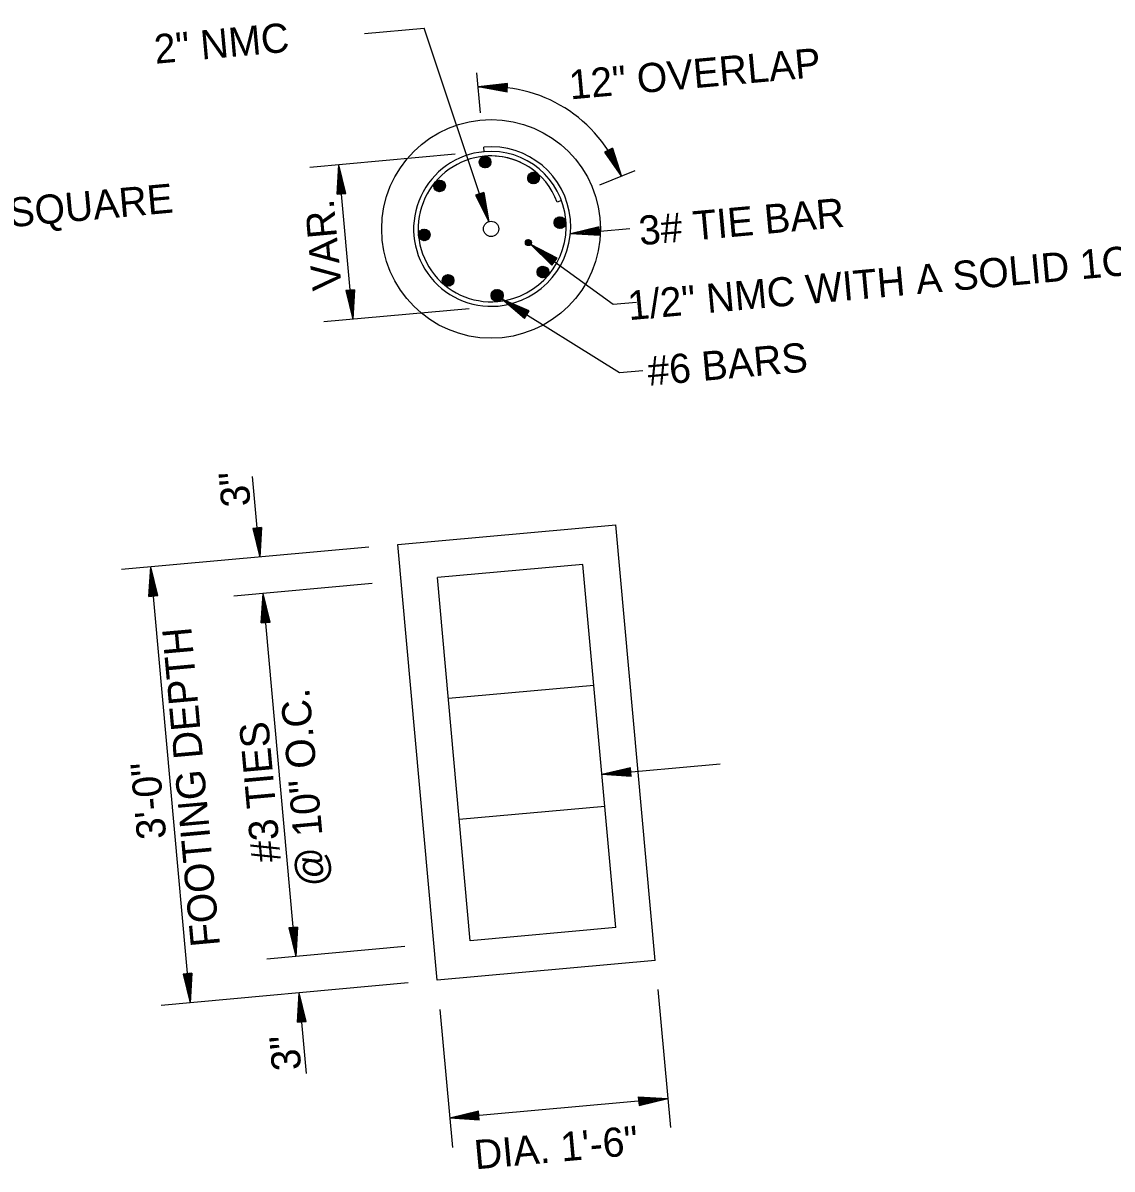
# Model space of a CAD drawing. Extents: x 1277218 to 1279252, y 196860 to 197529.
# Drawn here: x 1278789.6 to 1278960.9, y 197298.4 to 197478.8 of the extents above; entities that cross this region are included whole.
import ezdxf

# ---------------------------------------------------------------- set-up
doc = ezdxf.new("R2010")
doc.units = 0
doc.layers.add('R_Point Sym', color=7, linetype='Continuous')

msp = doc.modelspace()

# ---------------------------------------------------------------- linework, layer by layer
at = {"layer": 'R_Point Sym'}
for p, q in [((1278843.34, 197477.09), (1278852.69, 197477.93)), ((1278862.85, 197447.49), (1278852.69, 197477.93)), ((1278861.57, 197464.64), (1278861, 197470.9)), ((1278865.82, 197469.23), (1278861.21, 197468.71)), ((1278865.77, 197467.86), (1278861.21, 197468.71)), ((1278865.82, 197469.12), (1278861.98, 197468.68)), ((1278865.78, 197467.97), (1278861.98, 197468.68)), ((1278865.81, 197469), (1278862.76, 197468.66)), ((1278865.78, 197468.09), (1278862.76, 197468.66)), ((1278865.81, 197468.89), (1278863.53, 197468.63)), ((1278865.78, 197468.2), (1278863.53, 197468.63)), ((1278865.8, 197468.77), (1278864.31, 197468.6)), ((1278865.79, 197468.32), (1278864.31, 197468.6)), ((1278865.8, 197468.65), (1278865.07, 197468.57)), ((1278865.79, 197468.44), (1278865.07, 197468.57)), ((1278865.77, 197467.86), (1278865.82, 197469.23)), ((1278862.13, 197458.5), (1278862.06, 197459.22)), ((1278882.31, 197459.05), (1278881.07, 197458.44)), ((1278881.79, 197458.79), (1278882.01, 197458.09)), ((1278881.89, 197458.84), (1278882.35, 197457.4)), ((1278882, 197458.89), (1278882.69, 197456.71)), ((1278882.1, 197458.94), (1278883.03, 197456.02)), ((1278882.21, 197459), (1278883.38, 197455.31)), ((1278882.31, 197459.05), (1278883.71, 197454.62)), ((1278857.56, 197458.09), (1278834.7, 197456.02)), ((1278861.36, 197456.92), (1278862.07, 197457.77)), ((1278861.37, 197456.75), (1278862.23, 197457.79)), ((1278861.4, 197456.61), (1278862.38, 197457.78)), ((1278861.4, 197457.15), (1278861.85, 197457.68)), ((1278861.44, 197456.48), (1278862.51, 197457.76)), ((1278861.5, 197456.38), (1278862.63, 197457.72)), ((1278861.57, 197456.28), (1278862.73, 197457.67)), ((1278861.65, 197456.2), (1278862.83, 197457.61)), ((1278861.74, 197456.13), (1278862.92, 197457.53)), ((1278861.84, 197456.06), (1278862.99, 197457.45)), ((1278861.95, 197456.01), (1278863.06, 197457.35)), ((1278862.07, 197455.98), (1278863.12, 197457.24)), ((1278862.2, 197455.96), (1278863.16, 197457.11)), ((1278862.35, 197455.96), (1278863.19, 197456.96)), ((1278881.07, 197458.44), (1278883.71, 197454.62)), ((1278881.18, 197458.49), (1278883.38, 197455.31)), ((1278881.28, 197458.54), (1278883.03, 197456.02)), ((1278881.39, 197458.59), (1278882.69, 197456.71)), ((1278881.49, 197458.64), (1278882.35, 197457.4)), ((1278881.6, 197458.7), (1278882.01, 197458.09)), ((1278839, 197451.8), (1278839.27, 197456.43)), ((1278839.12, 197451.81), (1278839.34, 197455.67)), ((1278841.47, 197432.14), (1278839.27, 197456.43)), ((1278840.37, 197451.92), (1278839.27, 197456.43)), ((1278840.26, 197451.91), (1278839.34, 197455.67)), ((1278862.53, 197455.99), (1278863.19, 197456.79)), ((1278862.76, 197456.09), (1278863.13, 197456.53)), ((1278868.98, 197454.35), (1278869.74, 197455.26)), ((1278868.99, 197454.19), (1278869.9, 197455.27)), ((1278869, 197454.56), (1278869.54, 197455.2)), ((1278869.03, 197454.05), (1278870.04, 197455.26)), ((1278869.08, 197453.93), (1278870.16, 197455.23)), ((1278869.14, 197453.83), (1278870.28, 197455.19)), ((1278885.84, 197455.48), (1278880.26, 197453.23)), ((1278839.23, 197451.82), (1278839.41, 197454.88)), ((1278839.35, 197451.83), (1278839.48, 197454.12)), ((1278840.14, 197451.9), (1278839.41, 197454.88)), ((1278839.46, 197451.84), (1278839.55, 197453.35)), ((1278840.03, 197451.89), (1278839.48, 197454.12)), ((1278839.91, 197451.88), (1278839.55, 197453.35)), ((1278854.2, 197453.08), (1278855, 197454.03)), ((1278854.21, 197453.27), (1278854.81, 197453.98)), ((1278854.22, 197452.92), (1278855.15, 197454.04)), ((1278854.26, 197452.79), (1278855.29, 197454.02)), ((1278854.32, 197452.68), (1278855.41, 197453.99)), ((1278854.33, 197453.59), (1278854.52, 197453.81)), ((1278854.38, 197452.57), (1278855.52, 197453.94)), ((1278854.46, 197452.48), (1278855.63, 197453.89)), ((1278854.54, 197452.41), (1278855.72, 197453.82)), ((1278854.64, 197452.34), (1278855.8, 197453.74)), ((1278854.74, 197452.28), (1278855.87, 197453.65)), ((1278854.85, 197452.24), (1278855.94, 197453.54)), ((1278854.98, 197452.21), (1278855.99, 197453.42)), ((1278869.22, 197453.74), (1278870.38, 197455.13)), ((1278869.3, 197453.66), (1278870.47, 197455.07)), ((1278869.39, 197453.59), (1278870.56, 197454.99)), ((1278869.49, 197453.53), (1278870.63, 197454.9)), ((1278869.6, 197453.48), (1278870.7, 197454.8)), ((1278869.72, 197453.45), (1278870.75, 197454.69)), ((1278869.86, 197453.44), (1278870.79, 197454.55)), ((1278870.02, 197453.44), (1278870.81, 197454.4)), ((1278870.2, 197453.49), (1278870.8, 197454.21)), ((1278870.49, 197453.65), (1278870.69, 197453.9)), ((1278839, 197451.8), (1278840.37, 197451.92)), ((1278839.58, 197451.85), (1278839.62, 197452.58)), ((1278839.79, 197451.87), (1278839.62, 197452.58)), ((1278855.12, 197452.2), (1278856.02, 197453.29)), ((1278855.28, 197452.22), (1278856.04, 197453.13)), ((1278855.48, 197452.27), (1278856.02, 197452.92)), ((1278862.08, 197452.07), (1278860.77, 197451.64)), ((1278860.77, 197451.64), (1278862.85, 197447.49)), ((1278860.88, 197451.68), (1278862.61, 197448.22)), ((1278860.99, 197451.71), (1278862.37, 197448.97)), ((1278861.1, 197451.75), (1278862.13, 197449.7)), ((1278861.21, 197451.79), (1278861.89, 197450.44)), ((1278861.32, 197451.82), (1278861.65, 197451.17)), ((1278861.53, 197451.89), (1278861.65, 197451.17)), ((1278861.64, 197451.93), (1278861.89, 197450.44)), ((1278861.75, 197451.96), (1278862.13, 197449.7)), ((1278861.86, 197452), (1278862.37, 197448.97)), ((1278861.97, 197452.03), (1278862.61, 197448.22)), ((1278862.08, 197452.07), (1278862.85, 197447.49)), ((1278874.3, 197450.82), (1278873.63, 197450.55)), ((1278873.14, 197447.27), (1278873.96, 197448.25)), ((1278873.15, 197447.45), (1278873.78, 197448.22)), ((1278873.17, 197447.12), (1278874.11, 197448.26)), ((1278873.21, 197446.99), (1278874.25, 197448.24)), ((1278873.22, 197447.73), (1278873.53, 197448.09)), ((1278873.26, 197446.88), (1278874.37, 197448.2)), ((1278873.33, 197446.78), (1278874.48, 197448.16)), ((1278873.41, 197446.69), (1278874.58, 197448.1)), ((1278873.49, 197446.62), (1278874.67, 197448.02)), ((1278873.59, 197446.55), (1278874.75, 197447.94)), ((1278851.8, 197445.37), (1278852.59, 197446.32)), ((1278851.81, 197445.56), (1278852.4, 197446.27)), ((1278851.82, 197445.21), (1278852.74, 197446.32)), ((1278851.86, 197445.08), (1278852.88, 197446.31)), ((1278851.91, 197444.97), (1278853, 197446.28)), ((1278851.97, 197444.86), (1278853.12, 197446.23)), ((1278852.05, 197444.77), (1278853.22, 197446.17)), ((1278873.69, 197446.5), (1278874.82, 197447.85)), ((1278873.81, 197446.46), (1278874.88, 197447.74)), ((1278873.94, 197446.43), (1278874.93, 197447.62)), ((1278874.08, 197446.42), (1278874.96, 197447.48)), ((1278874.24, 197446.44), (1278874.97, 197447.32)), ((1278874.45, 197446.51), (1278874.94, 197447.1)), ((1278880.21, 197446.69), (1278875.7, 197445.59)), ((1278875.7, 197445.59), (1278885.05, 197446.44)), ((1278880.22, 197446.58), (1278876.46, 197445.66)), ((1278880.23, 197446.46), (1278877.25, 197445.73)), ((1278880.24, 197446.35), (1278878.01, 197445.8)), ((1278880.25, 197446.23), (1278878.78, 197445.87)), ((1278880.33, 197445.32), (1278880.21, 197446.69)), ((1278851.94, 197445.89), (1278852.09, 197446.08)), ((1278852.13, 197444.7), (1278853.31, 197446.11)), ((1278852.23, 197444.63), (1278853.39, 197446.03)), ((1278852.33, 197444.57), (1278853.47, 197445.93)), ((1278852.44, 197444.53), (1278853.53, 197445.83)), ((1278852.57, 197444.5), (1278853.58, 197445.71)), ((1278852.71, 197444.49), (1278853.62, 197445.58)), ((1278852.87, 197444.5), (1278853.63, 197445.42)), ((1278853.06, 197444.56), (1278853.61, 197445.22)), ((1278868.63, 197444.16), (1278869.06, 197444.68)), ((1278868.66, 197444.02), (1278869.2, 197444.67)), ((1278868.66, 197444.38), (1278868.85, 197444.61)), ((1278868.72, 197443.92), (1278869.32, 197444.63)), ((1278868.8, 197443.83), (1278869.41, 197444.57)), ((1278868.9, 197443.77), (1278869.49, 197444.48)), ((1278869.01, 197443.73), (1278869.55, 197444.37)), ((1278880.33, 197445.32), (1278875.7, 197445.59)), ((1278880.32, 197445.44), (1278876.46, 197445.66)), ((1278880.31, 197445.55), (1278877.25, 197445.73)), ((1278880.3, 197445.67), (1278878.01, 197445.8)), ((1278880.29, 197445.79), (1278878.78, 197445.87)), ((1278880.26, 197446.12), (1278879.55, 197445.94)), ((1278880.28, 197445.9), (1278879.55, 197445.94)), ((1278869.16, 197443.73), (1278869.58, 197444.23)), ((1278869.38, 197443.81), (1278869.54, 197444)), ((1278869.47, 197443.89), (1278882.44, 197434.49)), ((1278872.8, 197440.65), (1278869.47, 197443.89)), ((1278873.6, 197441.77), (1278869.47, 197443.89)), ((1278872.87, 197440.75), (1278870.09, 197443.44)), ((1278873.54, 197441.68), (1278870.09, 197443.44)), ((1278873.47, 197441.58), (1278870.74, 197442.98)), ((1278872.94, 197440.84), (1278870.74, 197442.98)), ((1278873, 197440.93), (1278871.36, 197442.54)), ((1278873.4, 197441.49), (1278871.36, 197442.54)), ((1278873.33, 197441.4), (1278871.99, 197442.08)), ((1278873.07, 197441.03), (1278871.99, 197442.08)), ((1278873.27, 197441.3), (1278872.61, 197441.64)), ((1278873.14, 197441.13), (1278872.61, 197441.64)), ((1278872.8, 197440.65), (1278873.6, 197441.77)), ((1278855.55, 197438.24), (1278856.31, 197439.15)), ((1278855.57, 197438.08), (1278856.47, 197439.17)), ((1278855.57, 197438.45), (1278856.11, 197439.1)), ((1278855.6, 197437.95), (1278856.61, 197439.16)), ((1278855.65, 197437.83), (1278856.74, 197439.13)), ((1278855.72, 197437.73), (1278856.85, 197439.09)), ((1278855.79, 197437.63), (1278856.95, 197439.03)), ((1278855.87, 197437.55), (1278857.05, 197438.96)), ((1278870.47, 197439.52), (1278871.26, 197440.47)), ((1278870.48, 197439.71), (1278871.07, 197440.42)), ((1278870.49, 197439.36), (1278871.42, 197440.47)), ((1278870.53, 197439.23), (1278871.55, 197440.46)), ((1278870.58, 197439.12), (1278871.68, 197440.43)), ((1278870.61, 197440.04), (1278870.77, 197440.24)), ((1278870.65, 197439.01), (1278871.79, 197440.38)), ((1278870.72, 197438.92), (1278871.89, 197440.33)), ((1278870.81, 197438.85), (1278871.98, 197440.26)), ((1278870.9, 197438.78), (1278872.06, 197440.18)), ((1278871, 197438.72), (1278872.14, 197440.09)), ((1278871.11, 197438.68), (1278872.2, 197439.98)), ((1278871.24, 197438.65), (1278872.25, 197439.86)), ((1278871.38, 197438.64), (1278872.29, 197439.73)), ((1278871.54, 197438.65), (1278872.3, 197439.57)), ((1278871.74, 197438.71), (1278872.28, 197439.37)), ((1278855.96, 197437.48), (1278857.13, 197438.89)), ((1278856.06, 197437.43), (1278857.21, 197438.8)), ((1278856.17, 197437.38), (1278857.27, 197438.7)), ((1278856.3, 197437.35), (1278857.32, 197438.58)), ((1278856.43, 197437.33), (1278857.36, 197438.45)), ((1278856.59, 197437.34), (1278857.39, 197438.29)), ((1278856.78, 197437.39), (1278857.37, 197438.1)), ((1278857.07, 197437.55), (1278857.26, 197437.79)), ((1278841.74, 197436.78), (1278840.37, 197436.65)), ((1278840.37, 197436.65), (1278841.47, 197432.14)), ((1278840.49, 197436.66), (1278841.4, 197432.91)), ((1278840.6, 197436.67), (1278841.33, 197433.69)), ((1278840.72, 197436.68), (1278841.26, 197434.45)), ((1278840.84, 197436.69), (1278841.19, 197435.23)), ((1278840.95, 197436.7), (1278841.12, 197435.99)), ((1278841.17, 197436.72), (1278841.12, 197435.99)), ((1278841.28, 197436.73), (1278841.19, 197435.23)), ((1278841.4, 197436.75), (1278841.26, 197434.45)), ((1278841.51, 197436.76), (1278841.33, 197433.69)), ((1278841.63, 197436.77), (1278841.4, 197432.91)), ((1278841.74, 197436.78), (1278841.47, 197432.14)), ((1278863.22, 197435.87), (1278864.02, 197436.83)), ((1278863.24, 197435.71), (1278864.18, 197436.84)), ((1278863.24, 197436.07), (1278863.82, 197436.77)), ((1278863.27, 197435.57), (1278864.32, 197436.83)), ((1278863.32, 197435.45), (1278864.45, 197436.8)), ((1278863.39, 197435.35), (1278864.56, 197436.76)), ((1278863.42, 197436.46), (1278863.47, 197436.53)), ((1278863.46, 197435.26), (1278864.67, 197436.71)), ((1278863.54, 197435.17), (1278864.76, 197436.64)), ((1278863.63, 197435.1), (1278864.85, 197436.57)), ((1278863.73, 197435.04), (1278864.93, 197436.48)), ((1278863.83, 197434.99), (1278864.99, 197436.38)), ((1278863.95, 197434.95), (1278865.05, 197436.27)), ((1278864.08, 197434.93), (1278865.1, 197436.15)), ((1278864.23, 197434.93), (1278865.13, 197436)), ((1278864.4, 197434.95), (1278865.13, 197435.83)), ((1278864.62, 197435.03), (1278865.09, 197435.61)), ((1278859.76, 197433.8), (1278836.9, 197431.73)), ((1278864.92, 197435.28), (1278883.42, 197423.76)), ((1278868.46, 197432.27), (1278864.92, 197435.28)), ((1278869.19, 197433.44), (1278864.92, 197435.28)), ((1278868.52, 197432.37), (1278865.57, 197434.87)), ((1278869.12, 197433.35), (1278865.57, 197434.87)), ((1278869.06, 197433.25), (1278866.24, 197434.46)), ((1278868.58, 197432.47), (1278866.24, 197434.46)), ((1278868.64, 197432.57), (1278866.89, 197434.06)), ((1278869, 197433.15), (1278866.89, 197434.06)), ((1278868.94, 197433.05), (1278867.55, 197433.65)), ((1278868.71, 197432.67), (1278867.55, 197433.65)), ((1278882.44, 197434.49), (1278886.11, 197434.82)), ((1278868.88, 197432.95), (1278868.21, 197433.24)), ((1278868.77, 197432.77), (1278868.21, 197433.24)), ((1278868.46, 197432.27), (1278869.19, 197433.44)), ((1278883.42, 197423.76), (1278887.08, 197424.09)), ((1278826.84, 197394.72), (1278825.69, 197407.42)), ((1278827.11, 197399.35), (1278825.74, 197399.23)), ((1278825.85, 197399.24), (1278826.77, 197395.48)), ((1278825.97, 197399.25), (1278826.7, 197396.27)), ((1278826.08, 197399.26), (1278826.63, 197397.03)), ((1278826.2, 197399.27), (1278826.56, 197397.8)), ((1278826.32, 197399.28), (1278826.49, 197398.57)), ((1278826.53, 197399.3), (1278826.49, 197398.57)), ((1278826.65, 197399.31), (1278826.56, 197397.8)), ((1278826.76, 197399.32), (1278826.63, 197397.03)), ((1278826.88, 197399.33), (1278826.7, 197396.27)), ((1278826.99, 197399.34), (1278826.77, 197395.48)), ((1278827.11, 197399.35), (1278826.84, 197394.72)), ((1278848.55, 197396.69), (1278882.83, 197399.79)), ((1278889.05, 197331.23), (1278882.83, 197399.79)), ((1278825.74, 197399.23), (1278826.84, 197394.72)), ((1278843.98, 197396.27), (1278805.12, 197392.75)), ((1278854.76, 197328.12), (1278848.55, 197396.69)), ((1278809.42, 197388.53), (1278809.7, 197393.17)), ((1278809.54, 197388.54), (1278809.76, 197392.4)), ((1278815.91, 197324.6), (1278809.7, 197393.17)), ((1278810.8, 197388.66), (1278809.7, 197393.17)), ((1278810.68, 197388.65), (1278809.76, 197392.4)), ((1278877.64, 197393.56), (1278854.78, 197391.49)), ((1278882.82, 197336.42), (1278877.64, 197393.56)), ((1278809.66, 197388.55), (1278809.84, 197391.62)), ((1278809.77, 197388.56), (1278809.91, 197390.86)), ((1278810.56, 197388.64), (1278809.84, 197391.62)), ((1278810.45, 197388.63), (1278809.91, 197390.86)), ((1278844.5, 197390.56), (1278822.78, 197388.59)), ((1278859.96, 197334.35), (1278854.78, 197391.49)), ((1278809.42, 197388.53), (1278810.8, 197388.66)), ((1278809.89, 197388.57), (1278809.98, 197390.08)), ((1278810.33, 197388.62), (1278809.98, 197390.08)), ((1278810, 197388.59), (1278810.04, 197389.32)), ((1278810.22, 197388.6), (1278810.04, 197389.32)), ((1278827.08, 197384.37), (1278827.36, 197389.01)), ((1278832.53, 197331.87), (1278827.36, 197389.01)), ((1278828.46, 197384.5), (1278827.36, 197389.01)), ((1278827.2, 197384.38), (1278827.42, 197388.24)), ((1278827.31, 197384.39), (1278827.5, 197387.46)), ((1278828.34, 197384.49), (1278827.42, 197388.24)), ((1278827.43, 197384.4), (1278827.56, 197386.69)), ((1278828.22, 197384.48), (1278827.5, 197387.46)), ((1278828.11, 197384.47), (1278827.56, 197386.69)), ((1278827.55, 197384.41), (1278827.64, 197385.92)), ((1278827.99, 197384.45), (1278827.64, 197385.92)), ((1278827.66, 197384.42), (1278827.7, 197385.16)), ((1278827.88, 197384.44), (1278827.7, 197385.16)), ((1278827.08, 197384.37), (1278828.46, 197384.5)), ((1278879.36, 197374.52), (1278856.51, 197372.44)), ((1278880.65, 197360.48), (1278899.26, 197362.17)), ((1278885.16, 197361.58), (1278880.65, 197360.48)), ((1278885.17, 197361.47), (1278881.41, 197360.55)), ((1278885.28, 197360.21), (1278885.16, 197361.58)), ((1278885.28, 197360.21), (1278880.65, 197360.48)), ((1278885.27, 197360.32), (1278881.41, 197360.55)), ((1278885.18, 197361.35), (1278882.2, 197360.62)), ((1278885.26, 197360.44), (1278882.2, 197360.62)), ((1278885.19, 197361.24), (1278882.96, 197360.69)), ((1278885.25, 197360.55), (1278882.96, 197360.69)), ((1278885.2, 197361.12), (1278883.73, 197360.76)), ((1278885.24, 197360.67), (1278883.73, 197360.76)), ((1278885.21, 197361), (1278884.5, 197360.83)), ((1278885.23, 197360.79), (1278884.5, 197360.83)), ((1278881.09, 197355.47), (1278858.23, 197353.4)), ((1278832.8, 197336.5), (1278831.43, 197336.37)), ((1278831.43, 197336.37), (1278832.53, 197331.87)), ((1278831.55, 197336.38), (1278832.46, 197332.63)), ((1278831.66, 197336.4), (1278832.39, 197333.41)), ((1278831.78, 197336.41), (1278832.32, 197334.18)), ((1278831.9, 197336.42), (1278832.25, 197334.95)), ((1278832.01, 197336.43), (1278832.18, 197335.71)), ((1278832.23, 197336.45), (1278832.18, 197335.71)), ((1278832.34, 197336.46), (1278832.25, 197334.95)), ((1278832.46, 197336.47), (1278832.32, 197334.18)), ((1278832.57, 197336.48), (1278832.39, 197333.41)), ((1278832.69, 197336.49), (1278832.46, 197332.63)), ((1278832.8, 197336.5), (1278832.53, 197331.87)), ((1278882.82, 197336.42), (1278859.96, 197334.35)), ((1278849.68, 197333.42), (1278827.96, 197331.45)), ((1278889.05, 197331.23), (1278854.76, 197328.12)), ((1278816.18, 197329.23), (1278814.81, 197329.11)), ((1278814.81, 197329.11), (1278815.91, 197324.6)), ((1278814.92, 197329.12), (1278815.84, 197325.36)), ((1278815.04, 197329.13), (1278815.77, 197326.15)), ((1278815.15, 197329.14), (1278815.7, 197326.91)), ((1278815.27, 197329.15), (1278815.63, 197327.68)), ((1278815.39, 197329.16), (1278815.56, 197328.45)), ((1278815.6, 197329.18), (1278815.56, 197328.45)), ((1278815.72, 197329.19), (1278815.63, 197327.68)), ((1278815.84, 197329.2), (1278815.7, 197326.91)), ((1278815.95, 197329.21), (1278815.77, 197326.15)), ((1278816.07, 197329.22), (1278815.84, 197325.36)), ((1278816.18, 197329.23), (1278815.91, 197324.6)), ((1278850.19, 197327.7), (1278811.34, 197324.18)), ((1278832.78, 197321.52), (1278833.05, 197326.15)), ((1278832.89, 197321.53), (1278833.12, 197325.39)), ((1278834.2, 197313.45), (1278833.05, 197326.15)), ((1278834.15, 197321.64), (1278833.05, 197326.15)), ((1278834.04, 197321.63), (1278833.12, 197325.39)), ((1278889.46, 197326.65), (1278891.43, 197304.94)), ((1278833.01, 197321.54), (1278833.19, 197324.6)), ((1278833.12, 197321.55), (1278833.26, 197323.84)), ((1278833.92, 197321.62), (1278833.19, 197324.6)), ((1278833.81, 197321.61), (1278833.26, 197323.84)), ((1278855.18, 197323.55), (1278857.15, 197301.83)), ((1278833.24, 197321.56), (1278833.33, 197323.07)), ((1278833.69, 197321.6), (1278833.33, 197323.07)), ((1278833.36, 197321.57), (1278833.4, 197322.3)), ((1278833.57, 197321.59), (1278833.4, 197322.3)), ((1278832.78, 197321.52), (1278834.15, 197321.64)), ((1278891.02, 197309.51), (1278856.73, 197306.41)), ((1278886.38, 197309.78), (1278891.02, 197309.51)), ((1278886.38, 197309.78), (1278886.51, 197308.41)), ((1278886.39, 197309.67), (1278890.25, 197309.44)), ((1278886.4, 197309.55), (1278889.47, 197309.37)), ((1278886.41, 197309.44), (1278888.71, 197309.3)), ((1278886.42, 197309.32), (1278887.93, 197309.23)), ((1278886.44, 197309.21), (1278887.17, 197309.16)), ((1278886.45, 197308.99), (1278887.17, 197309.16)), ((1278886.47, 197308.87), (1278887.93, 197309.23)), ((1278886.48, 197308.76), (1278888.71, 197309.3)), ((1278886.49, 197308.64), (1278889.47, 197309.37)), ((1278886.5, 197308.53), (1278890.25, 197309.44)), ((1278886.51, 197308.41), (1278891.02, 197309.51)), ((1278861.24, 197307.51), (1278856.73, 197306.41)), ((1278861.25, 197307.39), (1278857.5, 197306.47)), ((1278861.26, 197307.27), (1278858.28, 197306.55)), ((1278861.37, 197306.13), (1278861.24, 197307.51)), ((1278861.37, 197306.13), (1278856.73, 197306.41)), ((1278861.35, 197306.25), (1278857.5, 197306.47)), ((1278861.34, 197306.37), (1278858.28, 197306.55)), ((1278861.27, 197307.16), (1278859.04, 197306.62)), ((1278861.33, 197306.48), (1278859.04, 197306.62)), ((1278861.28, 197307.04), (1278859.82, 197306.69)), ((1278861.32, 197306.6), (1278859.82, 197306.69)), ((1278861.29, 197306.93), (1278860.58, 197306.75)), ((1278861.31, 197306.71), (1278860.58, 197306.75))]:
    msp.add_line(p, q, dxfattribs=at)
for centre, radius in [((1278863.23, 197446.36), 17.21), ((1278862.28, 197456.87), 0.918), ((1278869.9, 197454.35), 0.918), ((1278855.12, 197453.12), 0.918), ((1278874.06, 197447.34), 0.918), ((1278852.72, 197445.41), 0.918), ((1278863.23, 197446.36), 1.2), ((1278869.1, 197444.2), 0.478), ((1278856.47, 197438.25), 0.918), ((1278871.39, 197439.56), 0.918), ((1278864.18, 197435.88), 0.956)]:
    msp.add_circle(centre, radius, dxfattribs=at)
for centre, radius, start, end in [((1278863.2, 197446.72), 21.99, 21.0717, 95.1779), ((1278863.2, 197446.72), 12.55, 275.1779, 95.1779), ((1278863.23, 197446.36), 12.19, 95.1779, 275.1779), ((1278863.23, 197446.36), 11.47, 95.1779, 275.1779), ((1278863.2, 197446.72), 11.83, 275.1779, 95.1779), ((1278863.2, 197446.72), 11.12, 48.8673, 95.1779), ((1278863.2, 197446.72), 11.12, 20.1941, 95.1779)]:
    msp.add_arc(centre, radius, start, end, dxfattribs=at)

# ---------------------------------------------------------------- texts
for s, height, rotation, p in [('2" NMC', 4.59, 5.1779, (1278810.44, 197472.33)), ('12" OVERLAP', 4.5899, 5.1779, (1278875.7, 197466.72)), ('ANCHOR BASE SQUARE', 4.5899, 5.1779, (1278741.37, 197442.42)), ('VAR.', 4.59, 95.1779, (1278839.74, 197436.9)), ('3# TIE BAR', 4.59, 5.1779, (1278886.67, 197443.77)), (' 1/2" NMC WITH A SOLID 1C/#8 A.W.G., E.G.C.', 4.5899, 5.1779, (1278883.22, 197431.83)), ('#6 BARS', 4.59, 5.1779, (1278888.03, 197421.66)), ('3"', 4.59, 95.1779, (1278825.42, 197402.82)), ('FOOTING DEPTH', 4.5899, 95.1779, (1278820.6, 197333.6)), ('@ 10" O.C.', 4.59, 95.1779, (1278837.43, 197343.07)), ('#3 TIES', 4.59, 95.1779, (1278830.17, 197346.91)), ('3\'-0"', 4.59, 95.1779, (1278812.16, 197350.49)), ('3"', 4.59, 95.1779, (1278833.39, 197314.11)), ('DIA. 1\'-6"', 4.59, 5.1779, (1278860.77, 197298.37))]:
    msp.add_text(s, height=height, rotation=rotation, dxfattribs=at).set_placement(p)

doc.saveas('drawing.dxf')
